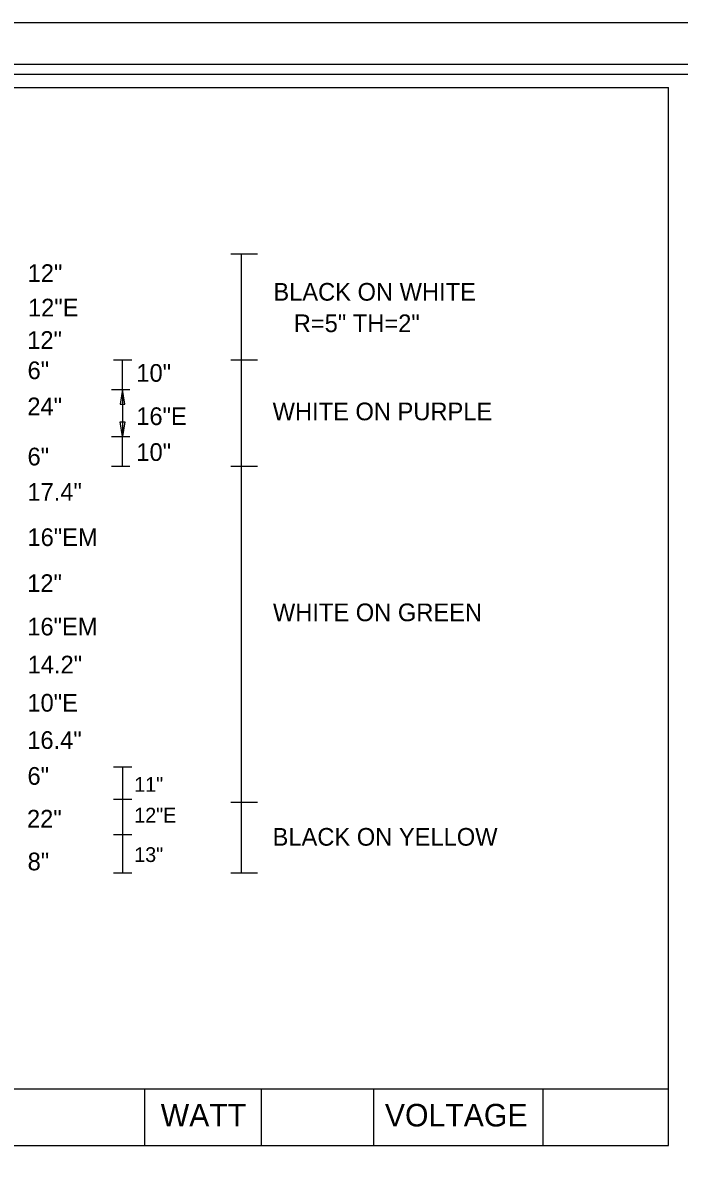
# Model space of a CAD drawing. Extents: x 119523 to 121850, y -23542 to -19972.
# Drawn here: x 120461.3 to 120683.8, y -22412.2 to -22027.7 of the extents above; entities that cross this region are included whole.
import ezdxf

# ---------------------------------------------------------------- set-up
doc = ezdxf.new("R2010")
doc.units = 0
for name, color, linetype in [('GSDims', 7, 'Continuous'), ('PlotBorder_dp', 7, 'Continuous'), ('SheetBorder_dp', 7, 'Continuous'), ('SheetLinesMisc2_dp', 7, 'Continuous'), ('TextMinor', 7, 'Continuous')]:
    doc.layers.add(name, color=color, linetype=linetype)

msp = doc.modelspace()

# ---------------------------------------------------------------- linework, layer by layer
at = {"layer": 'GSDims'}
for p, q in [((120531.78, -22106.11), (120540.88, -22106.11)), ((120535.26, -22106.11), (120535.26, -22142.11)), ((120491.98, -22142.11), (120498.23, -22142.11)), ((120495.1, -22152.11), (120495.1, -22142.11)), ((120531.78, -22142.11), (120540.88, -22142.11)), ((120535.26, -22142.11), (120535.26, -22316.11)), ((120491.35, -22152.11), (120497.6, -22152.11)), ((120491.35, -22152.11), (120497.6, -22152.11)), ((120495.1, -22152.11), (120495.1, -22168.11)), ((120491.35, -22168.11), (120497.6, -22168.11)), ((120491.35, -22168.11), (120497.6, -22168.11)), ((120495.1, -22178.11), (120495.1, -22168.11)), ((120491.35, -22178.11), (120497.6, -22178.11)), ((120531.78, -22178.11), (120540.88, -22178.11)), ((120491.98, -22280.1), (120498.23, -22280.1)), ((120495.1, -22280.1), (120495.1, -22316.11)), ((120491.98, -22291.11), (120498.23, -22291.11)), ((120531.78, -22292.11), (120540.88, -22292.11)), ((120491.98, -22303.11), (120498.23, -22303.11)), ((120491.98, -22316.11), (120498.23, -22316.11)), ((120531.78, -22316.11), (120540.88, -22316.11))]:
    msp.add_line(p, q, dxfattribs=at)
for points in [[(120495.1, -22152.11), (120494.27, -22157.11), (120495.93, -22157.11)], [(120495.1, -22168.11), (120494.27, -22163.11), (120495.93, -22163.11)]]:
    msp.add_lwpolyline(points, close=True, dxfattribs=at)
at = {"layer": 'PlotBorder_dp'}
msp.add_lwpolyline([(119522.87, -23522.86), (121850.2, -23522.86), (121850.2, -22027.72), (119522.87, -22027.72)], close=True, dxfattribs=at)
at = {"layer": 'SheetBorder_dp'}
msp.add_line((119600.45, -22041.83), (121772.62, -22041.83), dxfattribs=at)
at = {"layer": 'SheetLinesMisc2_dp'}
for p, q in [((119604.34, -22045.17), (121770.65, -22045.17)), ((119943.36, -22049.66), (120680.14, -22049.66)), ((120680.14, -22408.55), (120680.14, -22049.66)), ((119943.36, -22389.32), (120680.14, -22389.32)), ((120502.57, -22389.32), (120502.57, -22408.55)), ((120542.09, -22389.32), (120542.09, -22408.55)), ((120580.21, -22389.32), (120580.21, -22408.55)), ((120637.59, -22389.32), (120637.59, -22408.55)), ((119943.36, -22408.55), (120680.14, -22408.55))]:
    msp.add_line(p, q, dxfattribs=at)

# ---------------------------------------------------------------- texts
at = {"layer": 'GSDims'}
for s, height, p in [('12"', 6, (120462.93, -22115.68)), ('BLACK ON WHITE ', 6, (120546.22, -22122.01)), ('12"E', 6, (120463.04, -22127.36)), ('  R=5" TH=2"', 6, (120548.67, -22132.69)), ('12"', 6, (120462.79, -22138.36)), ('6"', 6, (120462.9, -22148.63)), ('10"', 6, (120499.78, -22149.53)), ('24"', 6, (120462.83, -22160.88)), ('16"E', 6, (120499.75, -22164.2)), ('WHITE ON PURPLE', 6, (120545.97, -22162.58)), ('10"', 6, (120499.78, -22176.37)), ('6"', 6, (120462.89, -22177.89)), ('17.4"', 6, (120462.85, -22189.9)), ('16"EM', 6, (120462.87, -22205.24)), ('12"', 6, (120462.78, -22220.84)), ('WHITE ON GREEN', 6, (120546.08, -22230.74)), ('16"EM', 6, (120462.81, -22235.57)), ('14.2"', 6, (120462.93, -22248.45)), ('10"E', 6, (120462.84, -22261.41)), ('16.4"', 6, (120462.8, -22274.05)), ('6"', 6, (120462.88, -22286.22)), ('11"', 5, (120499.06, -22288.61)), ('22"', 6, (120462.71, -22300.73)), ('12"E', 5, (120499.06, -22299.02)), ('BLACK ON YELLOW', 6, (120545.96, -22306.88)), ('8"', 6, (120462.93, -22315.24)), ('13"', 5, (120499.06, -22312.41))]:
    msp.add_text(s, height=height, rotation=360, dxfattribs=at).set_placement(p)
at = {"layer": 'TextMinor'}
for s, p in [('WATT', (120508.04, -22402.11)), ('VOLTAGE', (120584.02, -22402.11))]:
    msp.add_text(s, height=7.653, dxfattribs=at).set_placement(p)

doc.saveas('drawing.dxf')
